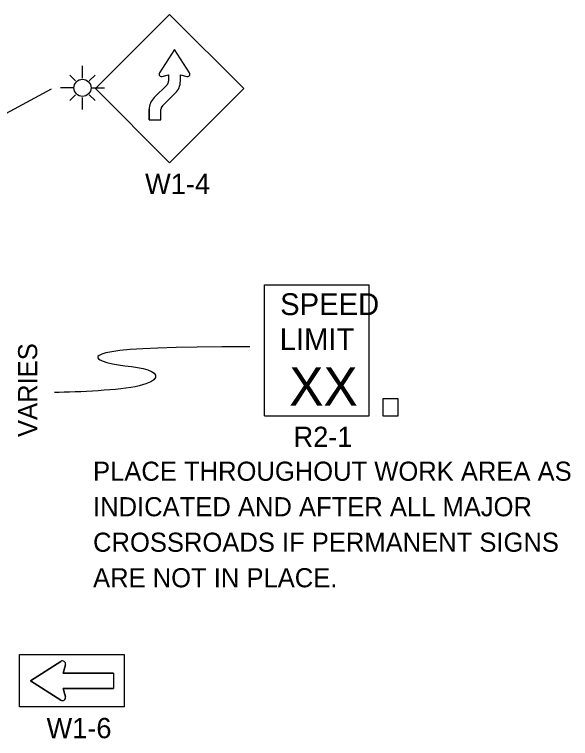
# Model space of a CAD drawing. Extents: x 16399 to 18476, y 7023 to 8321.
# Drawn here: x 17203.2 to 17406.8, y 7709.1 to 7974.1 of the extents above; entities that cross this region are included whole.
import ezdxf

# ---------------------------------------------------------------- set-up
doc = ezdxf.new("R2010")
doc.units = 0
doc.layers.add('TRAFFIC_SIGNS_PR', color=7, linetype='Continuous')
doc.layers.add('TYPICAL_TEXT_DIMEN_PR', color=7, linetype='Continuous')

msp = doc.modelspace()

# ---------------------------------------------------------------- linework, layer by layer
at = {"layer": 'TRAFFIC_SIGNS_PR'}
for p, q in [((17260, 7974.13), (17232.84, 7946.98)), ((17287.15, 7946.98), (17260, 7974.13)), ((17228.07, 7950.83), (17228.07, 7955.33)), ((17225.56, 7949.79), (17223.45, 7951.9)), ((17230.58, 7949.79), (17232.69, 7951.9)), ((17224.92, 7947.28), (17220.08, 7947.28)), ((17231.22, 7947.28), (17236.1, 7947.28)), ((17232.84, 7946.98), (17260, 7919.83)), ((17254.34, 7943.73), (17259.06, 7948.44)), ((17259.06, 7948.44), (17254.34, 7943.73)), ((17260, 7919.83), (17287.15, 7946.98)), ((17225.56, 7944.77), (17223.45, 7942.66)), ((17230.58, 7944.77), (17232.69, 7942.66)), ((17257.39, 7940.68), (17262.11, 7945.39)), ((17257.39, 7940.68), (17262.11, 7945.39)), ((17228.07, 7939.31), (17228.07, 7943.72)), ((17252.47, 7935.61), (17252.47, 7939.31)), ((17256.79, 7935.61), (17256.79, 7939.31)), ((17252.47, 7935.61), (17256.79, 7935.61)), ((17294.7, 7875.22), (17333.1, 7875.22)), ((17294.7, 7827.22), (17294.7, 7875.22)), ((17333.1, 7827.22), (17333.1, 7875.22)), ((17294.7, 7827.22), (17333.1, 7827.22)), ((17220.14, 7737.31), (17208.98, 7730.21)), ((17220.98, 7733.01), (17221.82, 7736.07)), ((17239.38, 7733.01), (17220.98, 7733.01)), ((17239.38, 7733.01), (17239.38, 7727.41)), ((17208.98, 7730.21), (17220.14, 7723.11)), ((17221.82, 7724.35), (17220.98, 7727.41)), ((17220.98, 7727.41), (17239.38, 7727.41))]:
    msp.add_line(p, q, dxfattribs=at)
for points in [[(17267.26, 7952.72), (17261.78, 7961.33), (17256.3, 7952.72)], [(17267.26, 7952.72), (17261.78, 7961.33), (17256.3, 7952.72)], [(17257.26, 7951.42), (17259.62, 7952.07), (17259.62, 7949.77)], [(17257.26, 7951.42), (17258.09, 7951.65), (17259.62, 7952.07), (17259.62, 7949.77)], [(17263.93, 7949.7), (17263.94, 7952.07), (17266.3, 7951.42)], [(17252.47, 7939.31), (17252.47, 7935.61), (17256.79, 7935.61), (17256.79, 7939.31)], [(17220.14, 7723.11), (17208.98, 7730.21), (17220.14, 7737.31)], [(17221.82, 7736.07), (17220.98, 7733.01), (17239.38, 7733.01), (17239.38, 7727.41), (17220.98, 7727.41), (17221.82, 7724.35)]]:
    msp.add_lwpolyline(points, dxfattribs=at)
for points in [[(17338.11, 7827.22), (17343.71, 7827.22), (17343.71, 7833.39), (17338.11, 7833.39)], [(17243.38, 7720.61), (17204.98, 7720.61), (17204.98, 7739.81), (17243.38, 7739.81)]]:
    msp.add_lwpolyline(points, close=True, dxfattribs=at)
msp.add_circle((17228.07, 7947.28), 3.15, dxfattribs=at)
for centre, radius, start, end in [((17257.03, 7952.25), 0.864, 147.5204, 285.3986), ((17257.03, 7952.25), 0.866, 147.5288, 285.3852), ((17266.53, 7952.26), 0.866, 254.6799, 32.2804), ((17257.77, 7949.77), 1.85, 314.2125, 0), ((17257.77, 7949.77), 1.85, 314.2123, 0.1238), ((17257.77, 7949.77), 6.17, 314.2125, 359.3819), ((17257.77, 7949.77), 6.17, 314.7687, 359.3755), ((17258.64, 7939.31), 6.17, 134.2117, 180), ((17258.64, 7939.31), 6.17, 134.2125, 180), ((17258.64, 7939.31), 6.17, 134.2125, 180), ((17258.64, 7939.31), 1.85, 132.372, 180), ((17258.64, 7939.31), 1.85, 134.2125, 180), ((17220.74, 7736.37), 1.12, 344.6731, 122.4696), ((17220.74, 7736.37), 1.12, 344.6731, 122.4696), ((17220.74, 7724.06), 1.12, 237.5304, 15.3269), ((17220.74, 7724.06), 1.12, 237.5304, 15.3269)]:
    msp.add_arc(centre, radius, start, end, dxfattribs=at)
at = {"layer": 'TYPICAL_TEXT_DIMEN_PR'}
msp.add_line((17216.55, 7946.85), (17184.06, 7929.11), dxfattribs=at)
msp.add_open_spline([(17289.35, 7852.47), (17231.05, 7852.74), (17231.05, 7845.47), (17256.23, 7845.47), (17256.23, 7837.07), (17226.67, 7835.91), (17217.78, 7835.72)], degree=3, dxfattribs=at)

# ---------------------------------------------------------------- texts
at = {"layer": 'TRAFFIC_SIGNS_PR'}
for s, height, p in [('W1-4', 7.44, (17251, 7908.39)), ('SPEED', 8, (17300.46, 7864.08)), ('LIMIT', 8, (17300.3, 7851.28)), ('XX', 14.031, (17303.81, 7830.98)), ('R2-1', 7.44, (17305.37, 7815.78)), ('PLACE THROUGHOUT WORK AREA AS', 7, (17231.95, 7803.43)), ('INDICATED AND AFTER ALL MAJOR', 7, (17231.95, 7790.43)), ('CROSSROADS IF PERMANENT SIGNS', 7, (17231.95, 7777.43)), ('ARE NOT IN PLACE.', 7, (17231.95, 7764.43)), ('W1-6', 7.44, (17214.92, 7709.17))]:
    msp.add_text(s, height=height, dxfattribs=at).set_placement(p)
at = {"layer": 'TYPICAL_TEXT_DIMEN_PR'}
msp.add_text('VARIES', height=7, rotation=90, dxfattribs=at).set_placement((17211.49, 7819.45))

doc.saveas('drawing.dxf')
